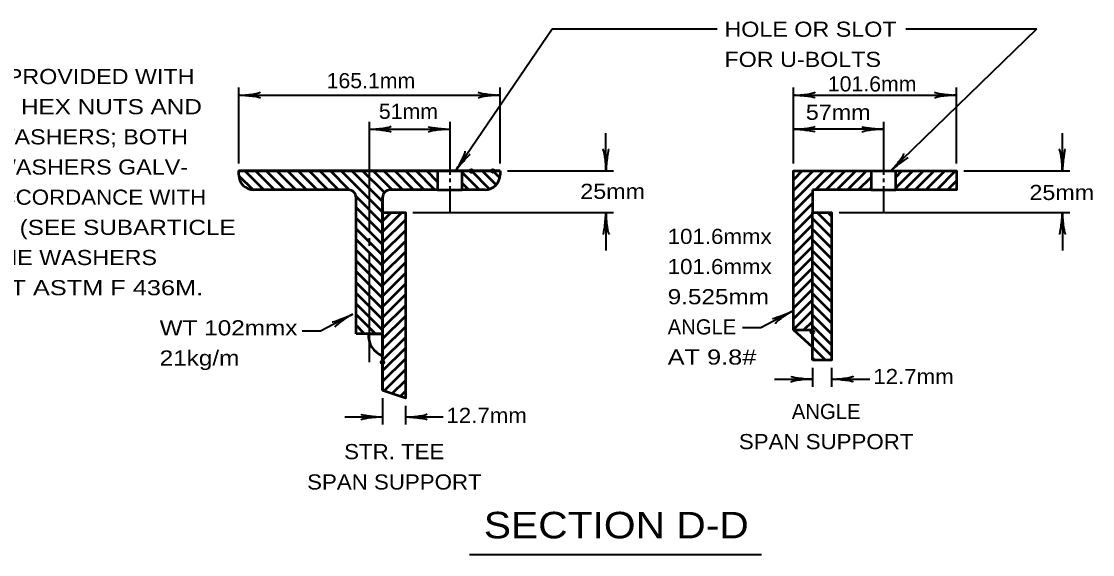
# Model space of a CAD drawing. Extents: x -29 to 827, y -14 to 530.
# Drawn here: x 457.6 to 628.7, y 196.6 to 281.8 of the extents above; entities that cross this region are included whole.
import ezdxf
from ezdxf.enums import TextEntityAlignment as Align

# ---------------------------------------------------------------- set-up
doc = ezdxf.new("R2010")
doc.units = 0
doc.header["$LTSCALE"] = 0.97
doc.header["$PDMODE"] = 32
doc.header["$PDSIZE"] = 0.485
doc.layers.add('1', color=7, linetype='Continuous', lineweight=53)

msp = doc.modelspace()

# ---------------------------------------------------------------- linework, layer by layer
at = {"layer": '1', "lineweight": 35}
for p, q in [((526.977, 257.8898), (542.4287, 280.5596)), ((542.4287, 280.5596), (568.7428, 280.5596)), ((596.4605, 257.8898), (619.8097, 280.5596)), ((598.9191, 280.5596), (619.8097, 280.5596)), ((492.3456, 259.0898), (492.3456, 271.1858)), ((534.0816, 259.0898), (534.0816, 271.1858)), ((580.9536, 259.0898), (580.9536, 271.1858)), ((606.9696, 259.0898), (606.9696, 271.1858)), ((492.3456, 269.9858), (534.0816, 269.9858)), ((580.9536, 269.9858), (606.9696, 269.9858)), ((513.2016, 265.7378), (513.2016, 248.3618)), ((526.0656, 265.7378), (526.0656, 257.2658)), ((595.3296, 265.7378), (595.3296, 257.2658)), ((513.2016, 264.5378), (526.0656, 264.5378)), ((551.0016, 257.8898), (551.0016, 263.9378)), ((595.3296, 264.5378), (580.9536, 264.5378)), ((623.9136, 257.8898), (623.9136, 263.9378)), ((526.0656, 256.6658), (526.0656, 256.0658)), ((535.2816, 257.8898), (552.2256, 257.8898)), ((595.3296, 256.6658), (595.3296, 256.0658)), ((608.1696, 257.8898), (625.1136, 257.8898)), ((526.0656, 255.4658), (526.0656, 251.2178)), ((595.3296, 255.4658), (595.3296, 251.2178)), ((520.1616, 251.2178), (552.2256, 251.2178)), ((551.0016, 251.2178), (551.0016, 245.1698)), ((588.2256, 251.2178), (625.1136, 251.2178)), ((623.9136, 251.2178), (623.9136, 245.1698)), ((513.2016, 247.1378), (513.2016, 245.9378)), ((513.2016, 244.7138), (513.2016, 227.3378)), ((583.9776, 226.4258), (583.9776, 223.4018)), ((587.0016, 226.4258), (587.0016, 223.4018)), ((577.9296, 224.6258), (583.9776, 224.6258)), ((587.0736, 224.6258), (593.1216, 224.6258)), ((515.3136, 221.6018), (515.3136, 217.3538)), ((518.9616, 220.3778), (518.9616, 217.3538)), ((509.2656, 218.5778), (515.3136, 218.5778)), ((518.9616, 218.5778), (525.0096, 218.5778))]:
    msp.add_line(p, q, dxfattribs=at)
at = {"layer": '1'}
for p, q in [((534.0816, 257.8898), (492.3456, 257.8898)), ((494.6256, 254.8658), (492.3456, 257.1218)), ((496.3296, 254.8658), (493.3056, 257.8898)), ((498.0336, 254.8658), (495.0096, 257.8898)), ((499.7376, 254.8658), (496.7136, 257.8898)), ((501.4656, 254.8658), (498.4416, 257.8898)), ((503.1696, 254.8658), (500.1456, 257.8898)), ((504.8736, 254.8658), (501.8496, 257.8898)), ((506.6016, 254.8658), (503.5776, 257.8898)), ((508.3056, 254.8658), (505.2816, 257.8898)), ((510.0096, 254.8418), (506.9856, 257.8898)), ((515.3136, 251.2658), (508.6896, 257.8898)), ((515.3136, 252.9698), (510.4176, 257.8898)), ((515.6016, 254.4098), (512.1216, 257.8898)), ((516.8496, 254.8658), (513.8256, 257.8898)), ((518.5536, 254.8658), (515.5296, 257.8898)), ((520.2816, 254.8658), (517.2576, 257.8898)), ((521.9856, 254.8658), (518.9616, 257.8898)), ((523.6896, 254.8658), (520.6656, 257.8898)), ((524.0976, 256.1618), (522.3936, 257.8898)), ((528.0336, 254.8658), (528.0336, 257.8898)), ((530.8176, 254.8658), (528.0336, 257.6498)), ((532.4088, 254.9786), (529.4976, 257.8898)), ((533.4491, 255.6423), (531.2016, 257.8898)), ((534.0332, 256.7862), (532.9296, 257.8898)), ((534.0816, 257.8898), (534.0816, 257.2658)), ((580.9536, 256.4738), (582.3456, 257.8898)), ((580.9536, 254.7698), (584.0736, 257.8898)), ((580.9536, 253.0658), (585.7776, 257.8898)), ((584.4576, 254.8658), (587.4816, 257.8898)), ((586.1856, 254.8658), (589.2096, 257.8898)), ((587.8896, 254.8658), (590.9136, 257.8898)), ((589.5936, 254.8658), (592.6176, 257.8898)), ((591.2976, 254.8658), (593.3616, 256.9058)), ((593.3616, 257.8898), (597.2976, 257.8898)), ((597.2976, 256.8818), (598.2816, 257.8898)), ((597.2976, 255.1778), (600.0096, 257.8898)), ((598.6896, 254.8658), (601.7136, 257.8898)), ((600.3936, 254.8658), (603.4176, 257.8898)), ((602.0976, 254.8658), (605.1216, 257.8898)), ((603.8256, 254.8658), (606.8496, 257.8898)), ((529.1136, 254.8658), (528.0336, 255.9458)), ((593.0256, 254.8658), (593.3616, 255.2018)), ((605.5296, 254.8658), (606.9696, 256.2818)), ((509.8896, 254.8658), (494.7456, 254.8658)), ((515.3136, 249.5378), (511.0896, 253.7858)), ((511.0896, 231.8738), (511.0896, 253.6418)), ((515.3136, 253.6418), (515.3136, 251.2178)), ((515.3136, 253.6418), (515.3136, 231.8738)), ((515.3136, 232.1747), (515.3136, 253.6418)), ((524.0976, 254.8658), (528.0336, 254.8658)), ((531.6816, 254.8658), (528.0336, 254.8658)), ((580.9536, 251.3618), (583.9776, 254.3858)), ((593.3616, 254.8658), (597.2976, 254.8658)), ((515.3136, 247.8338), (511.0896, 252.0578)), ((580.9536, 249.6338), (583.9776, 252.6578)), ((515.3136, 246.1298), (511.0896, 250.3538)), ((515.3136, 249.8738), (516.6816, 251.2178)), ((515.3136, 248.1698), (518.3856, 251.2178)), ((515.3136, 246.4418), (518.9616, 250.0898)), ((580.9536, 247.9298), (583.9776, 250.9538)), ((583.9776, 232.4738), (583.9776, 251.2178)), ((587.0016, 247.2338), (583.9776, 250.2578)), ((587.0016, 248.9378), (584.7216, 251.2178)), ((587.0016, 250.6658), (586.4496, 251.2178)), ((515.3136, 244.4018), (511.0896, 248.6498)), ((515.3136, 244.7378), (518.9616, 248.3618)), ((580.9536, 246.2258), (583.9776, 249.2498)), ((587.0016, 245.5298), (583.9776, 248.5538)), ((515.3136, 242.6978), (511.0896, 246.9458)), ((515.3136, 243.0338), (518.9616, 246.6578)), ((580.9536, 244.5218), (583.9776, 247.5458)), ((587.0016, 243.8258), (583.9776, 246.8498)), ((515.3136, 240.9938), (511.0896, 245.2178)), ((515.3136, 241.3298), (518.9616, 244.9538)), ((580.9536, 242.7938), (583.9776, 245.8178)), ((587.0016, 242.0978), (583.9776, 245.1218)), ((515.3136, 239.2898), (511.0896, 243.5138)), ((515.3136, 239.6018), (518.9616, 243.2258)), ((580.9536, 241.0898), (583.9776, 244.1138)), ((587.0016, 240.3938), (583.9776, 243.4178)), ((515.3136, 237.5618), (511.0896, 241.8098)), ((515.3136, 237.8978), (518.9616, 241.5218)), ((580.9536, 239.3858), (583.9776, 242.4098)), ((587.0016, 238.6898), (583.9776, 241.7138)), ((515.3136, 235.8578), (511.0896, 240.0818)), ((515.3136, 236.1938), (518.9616, 239.8178)), ((580.9536, 237.6578), (583.9776, 240.6818)), ((587.0016, 236.9858), (583.9776, 240.0098)), ((515.3136, 234.1538), (511.0896, 238.3778)), ((515.3136, 234.4658), (518.9616, 238.1138)), ((580.9536, 235.9538), (583.9776, 238.9778)), ((587.0016, 235.2578), (583.9776, 238.2818)), ((515.3136, 232.4498), (511.0896, 236.6738)), ((515.3136, 232.7618), (518.9616, 236.3858)), ((580.9536, 234.2498), (583.9776, 237.2738)), ((587.0016, 233.5538), (583.9776, 236.5778)), ((514.1856, 231.8738), (511.0896, 234.9698)), ((515.3136, 231.0578), (518.9616, 234.6818)), ((580.9536, 232.5458), (583.9776, 235.5698)), ((587.0016, 231.8498), (583.9776, 234.8738)), ((512.4576, 231.8738), (511.0896, 233.2418)), ((515.3136, 229.3538), (518.9616, 232.9778)), ((582.6096, 232.4738), (583.9776, 233.8418)), ((587.0016, 230.1218), (583.9776, 233.1458)), ((515.3136, 231.8738), (511.0896, 231.8738)), ((515.3136, 222.8018), (515.3136, 231.8738)), ((515.3136, 227.6258), (518.9616, 231.2738)), ((583.9776, 227.6498), (583.9776, 232.4738)), ((587.0016, 228.4178), (583.9776, 231.4418)), ((515.3136, 225.9218), (518.9616, 229.5458)), ((586.0896, 227.6498), (583.9776, 229.7378)), ((515.3136, 228.0996), (515.3136, 222.8018)), ((515.3136, 224.2178), (518.9616, 227.8418)), ((584.3616, 227.6498), (583.9776, 228.0338)), ((515.5536, 222.7298), (518.9616, 226.1378)), ((516.8256, 222.2978), (518.9616, 224.4098)), ((518.1216, 221.8658), (518.9616, 222.7058))]:
    msp.add_line(p, q, dxfattribs=at)
at = {"layer": '1', "lineweight": 40}
msp.add_line((529.1856, 196.5938), (575.8416, 196.5938), dxfattribs=at)
at = {"layer": '1'}
for points in [[(492.3456, 257.2658), (492.3456, 257.8898), (534.0816, 257.8898)], [(524.0976, 257.8898), (524.0976, 254.8658), (516.5376, 254.8658)], [(580.9536, 232.4738), (580.9536, 257.8898), (593.3616, 257.8898), (593.3616, 254.8658), (583.9776, 254.8658)], [(583.9776, 254.8658), (583.9776, 251.2178), (587.0016, 251.2178), (587.0016, 227.6498), (583.9776, 227.6498)], [(515.3136, 251.2178), (518.9616, 251.2178), (518.9616, 221.6018), (515.3136, 222.8018)], [(513.0541, 231.8738), (515.3136, 231.8738), (515.3136, 228.3378)]]:
    msp.add_lwpolyline(points, dxfattribs=at)
for points in [[(597.2976, 254.8658), (597.2976, 257.8898), (606.9696, 257.8898), (606.9696, 254.8658)], [(580.9536, 232.4738), (583.9776, 232.4738), (583.9776, 229.7486)]]:
    msp.add_lwpolyline(points, close=True, dxfattribs=at)
at = {"layer": '1', "lineweight": 35}
for points in [[(510.557, 235.0131), (505.421, 232.2771), (502.469, 232.2771)], [(580.9056, 235.5458), (575.7456, 232.8338), (572.8176, 232.8338)]]:
    msp.add_lwpolyline(points, dxfattribs=at)
at = {"layer": '1'}
for centre, radius, start, end in [((494.7456, 257.2658), 2.4, 180, 270), ((531.6816, 257.2658), 2.4, 270, 0), ((509.8789, 253.6453), 1.2096, 0, 90), ((516.5317, 253.6453), 1.2096, 90, 180), ((516.6215, 231.6635), 3.5736, 176.62555, 248.53197)]:
    msp.add_arc(centre, radius, start, end, dxfattribs=at)
at = {"layer": '1', "lineweight": 40}
for centre, major_axis, ratio, start_param, end_param in [((493.6596, 270.3091), (-2.16, -0.1889), 0.122415, 0.89635335, 3.14159265), ((493.6596, 270.3091), (-2.16, -0.1889), 0.122415, 0.89635335, 3.14159265), ((532.7155, 270.2309), (2.1246, -0.2125), 0.07063, 3.14071475, 5.41810995), ((493.695, 269.719), (-2.1246, 0.2125), 0.07063, 3.14071475, 5.41810995), ((493.695, 269.719), (-2.1246, 0.2125), 0.07063, 3.14071475, 5.41810995), ((532.7509, 269.6407), (2.16, 0.1889), 0.122415, 0.89635335, 3.14159265), ((514.5606, 264.2758), (-2.1246, 0.2125), 0.07063, 3.14071475, 5.41810995), ((514.5606, 264.2758), (-2.1246, 0.2125), 0.07063, 3.14071475, 5.41810995), ((514.5252, 264.8659), (-2.16, -0.1889), 0.122415, 0.89635335, 3.14159265), ((514.5252, 264.8659), (-2.16, -0.1889), 0.122415, 0.89635335, 3.14159265), ((524.7373, 264.1975), (2.16, 0.1889), 0.122415, 0.89635335, 3.14159265), ((524.7019, 264.7877), (2.1246, -0.2125), 0.07063, 3.14071475, 5.41810995), ((582.317, 264.2758), (-2.1246, 0.2125), 0.07063, 3.14071475, 5.41810995), ((582.317, 264.2758), (-2.1246, 0.2125), 0.07063, 3.14071475, 5.41810995), ((582.2815, 264.8659), (-2.16, -0.1889), 0.122415, 0.89635335, 3.14159265), ((582.2815, 264.8659), (-2.16, -0.1889), 0.122415, 0.89635335, 3.14159265), ((594.0057, 264.1975), (2.16, 0.1889), 0.122415, 0.89635335, 3.14159265), ((593.9702, 264.7877), (2.1246, -0.2125), 0.07063, 3.14071475, 5.41810995), ((527.4405, 259.1585), (-1.052, -1.8762), 0.122415, 0.89635335, 3.14159265), ((527.4405, 259.1585), (-1.052, -1.8762), 0.122415, 0.89635335, 3.14159265), ((527.9441, 258.8578), (1.3613, 1.6229), 0.07063, 6.28230741, 8.55970261), ((527.9441, 258.8578), (1.3613, 1.6229), 0.07063, 6.28230741, 8.55970261), ((550.671, 259.1988), (0.1889, -2.16), 0.122415, 0.89635335, 3.14159265), ((551.2612, 259.2343), (-0.2125, -2.1246), 0.07063, 3.14071475, 5.41810995), ((597.169, 259.0398), (-1.4069, -1.6271), 0.122415, 0.89635335, 3.14159265), ((623.5682, 259.1988), (0.1889, -2.16), 0.122415, 0.89635335, 3.14159265), ((623.5682, 259.1988), (0.1889, -2.16), 0.122415, 0.89635335, 3.14159265), ((624.1584, 259.2343), (-0.2125, -2.1246), 0.07063, 3.14071475, 5.41810995), ((624.1584, 259.2343), (-0.2125, -2.1246), 0.07063, 3.14071475, 5.41810995), ((597.6021, 258.6443), (1.6591, 1.317), 0.07063, 6.28230741, 8.55970261), ((550.7493, 249.8708), (0.2125, 2.1246), 0.07063, 3.14071475, 5.41810995), ((551.3395, 249.9062), (-0.1889, 2.16), 0.122415, 0.89635335, 3.14159265), ((623.6465, 249.8708), (0.2125, 2.1246), 0.07063, 3.14071475, 5.41810995), ((624.2366, 249.9062), (-0.1889, 2.16), 0.122415, 0.89635335, 3.14159265), ((509.2314, 234.5963), (-1.977, -0.8065), 0.07063, 6.28230741, 8.55970261), ((509.5389, 234.0913), (1.8204, 1.1778), 0.122415, 0.89635335, 3.14159265), ((579.5797, 235.1399), (-1.977, -0.8065), 0.07063, 6.28230741, 8.55970261), ((579.8873, 234.6349), (1.8204, 1.1778), 0.122415, 0.89635335, 3.14159265), ((582.6657, 224.2807), (2.16, 0.1889), 0.122415, 0.89635335, 3.14159265), ((582.6657, 224.2807), (2.16, 0.1889), 0.122415, 0.89635335, 3.14159265), ((582.6302, 224.8709), (2.1246, -0.2125), 0.07063, 3.14071475, 5.41810995), ((582.6302, 224.8709), (2.1246, -0.2125), 0.07063, 3.14071475, 5.41810995), ((588.4198, 224.359), (-2.1246, 0.2125), 0.07063, 3.14071475, 5.41810995), ((588.3844, 224.9491), (-2.16, -0.1889), 0.122415, 0.89635335, 3.14159265), ((513.9667, 218.8229), (2.1246, -0.2125), 0.07063, 3.14071475, 5.41810995), ((513.9667, 218.8229), (2.1246, -0.2125), 0.07063, 3.14071475, 5.41810995), ((520.2708, 218.9011), (-2.16, -0.1889), 0.122415, 0.89635335, 3.14159265), ((514.0021, 218.2327), (2.16, 0.1889), 0.122415, 0.89635335, 3.14159265), ((514.0021, 218.2327), (2.16, 0.1889), 0.122415, 0.89635335, 3.14159265), ((520.3062, 218.311), (-2.1246, 0.2125), 0.07063, 3.14071475, 5.41810995)]:
    msp.add_ellipse(centre, major_axis=major_axis, ratio=ratio, start_param=start_param, end_param=end_param, dxfattribs=at)
at = {"layer": '1', "lineweight": 35}
for centre, major_axis, ratio, start_param, end_param in [((582.2815, 270.3091), (-2.16, -0.1889), 0.122415, 0.89635335, 3.14159265), ((582.2815, 270.3091), (-2.16, -0.1889), 0.122415, 0.89635335, 3.14159265), ((605.6126, 270.2309), (2.1246, -0.2125), 0.07063, 3.14071475, 5.41810995), ((605.6126, 270.2309), (2.1246, -0.2125), 0.07063, 3.14071475, 5.41810995), ((582.317, 269.719), (-2.1246, 0.2125), 0.07063, 3.14071475, 5.41810995), ((582.317, 269.719), (-2.1246, 0.2125), 0.07063, 3.14071475, 5.41810995), ((605.6481, 269.6407), (2.16, 0.1889), 0.122415, 0.89635335, 3.14159265), ((605.6481, 269.6407), (2.16, 0.1889), 0.122415, 0.89635335, 3.14159265)]:
    msp.add_ellipse(centre, major_axis=major_axis, ratio=ratio, start_param=start_param, end_param=end_param, dxfattribs=at)
at = {"layer": '1'}
for p in [(529.4976, 257.8898), (532.9296, 257.8898), (583.9776, 232.1378), (515.3136, 227.3138)]:
    msp.add_point(p, dxfattribs=at)

# ---------------------------------------------------------------- texts
for s, height, width, p in [('HOLE OR SLOT', 2.419, 1.15, (569.9253, 279.3075)), ('FOR U-BOLTS', 2.419, 1.15, (569.9253, 274.4883)), ('EACH BOLT PROVIDED WITH', 2.419, 1.15, (433.1873, 271.754)), ('165.1mm', 2.419, 1.05, (506.381, 271.0908)), ('101.6mm', 2.419, 1.05, (586.437, 270.5762)), ('TWO HEAVY HEX NUTS AND', 2.419, 1.2, (433.1873, 266.9348)), ('51mm', 2.419, 1.05, (514.7336, 266.1938)), ('57mm', 2.419, 1.15, (582.9269, 266.0354)), ('TWO FLAT WASHERS; BOTH', 2.419, 1.15, (433.1873, 262.1156)), ('NUTS AND WASHERS GALV-', 2.419, 1.15, (433.1873, 257.2964)), ('ANIZED IN ACCORDANCE WITH', 2.419, 1.1, (433.1873, 252.4772)), ('25mm', 2.419, 1.15, (546.9032, 253.4114)), ('25mm', 2.419, 1.15, (618.6357, 253.2338)), ('ASTM A 153. (SEE SUBARTICLE', 2.419, 1.2, (433.1873, 247.658)), ('101.6mmx', 2.419, 1.1, (560.8576, 246.2161)), ('658.2.2.1). THE WASHERS', 2.419, 1.15, (433.1873, 242.8388)), ('101.6mmx', 2.419, 1.1, (560.8576, 241.3969)), ('SHALL MEET ASTM F 436M.', 2.419, 1.25, (433.1873, 238.0196)), ('9.525mm', 2.419, 1.2, (560.8576, 236.5777)), ('WT 102mmx', 2.419, 1.2, (479.7143, 231.61)), ('21kg/m', 2.419, 1.2, (479.7143, 226.7908)), ('AT 9.8#', 2.419, 1.25, (560.8576, 226.9393)), ('12.7mm', 2.419, 1.1, (593.6951, 223.8337)), ('12.7mm', 2.419, 1.1, (525.5136, 217.6178)), ('SECTION D-D', 4.234, 1.15, (531.4896, 199.1858))]:
    msp.add_text(s, height=height, dxfattribs=dict(at, width=width)).set_placement(p)
msp.add_text('ANGLE', height=2.419, dxfattribs=at).set_placement((560.8576, 231.7585))
msp.add_text('ANGLE', height=2.419, dxfattribs=at).set_placement((586.168, 218.2506), align=Align.CENTER)
at = {"layer": '1', "width": 1.1}
for s, p in [('SPAN SUPPORT', (586.168, 213.4314)), ('STR. TEE', (517.1865, 211.8338)), ('SPAN SUPPORT', (517.2075, 206.9858))]:
    msp.add_text(s, height=2.419, dxfattribs=at).set_placement(p, align=Align.CENTER)

doc.saveas('drawing.dxf')
